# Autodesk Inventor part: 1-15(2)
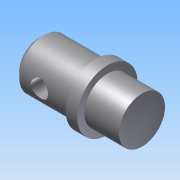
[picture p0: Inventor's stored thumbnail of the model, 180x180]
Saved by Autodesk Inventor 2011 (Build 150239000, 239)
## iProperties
Created: 2014-02
Part Number: 1-15(2)
Document SubType Name: Modeling
Designer: Administrator
Density: 1 g/cm^3
Author: Administrator
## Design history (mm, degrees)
sketch "草图1"
  geometry: L1 (-8.931, 4.3)-(-8.931, 0); L2 (-8.931, 4.3)-(1.069, 4.3); L3 (1.069, 4.3)-(1.069, 5.245); L4 (1.069, 5.245)-(3.069, 5.245); L5 (3.069, 5.245)-(3.069, 4); L6 (3.069, 4)-(9.069, 4); L7 (-8.931, 0)-(9.069, 0); L8 (9.069, 0)-(9.069, 4); C1 r 1.5 at (-5.572, 0); 2 further points
  constraints: 16 end point, 4 parallel, 3 perpendicular, 1 centre point, 1 horizontal alignment, 1 point on line
  dimensions: "d1" = 3 diameter of C1; "d6" = 4 distance of L7.end L6.end; "d8" = 4.3 distance between parallel lines of L7 L2; "d10" = 10 distance of L1.start L2.end; "d11" = 18 distance between parallel lines of L8 L1; "d13" = 2 distance of L3.end L4.end
revolve "旋转1" sketch "草图1" stored, may be unused: angle "d0" = 90 deg
node "工作平面1"
sketch "草图2"
  geometry: L1 (10.036, 4.077)-(10.036, -4.077) reference; L2 (8.931, 4.3)-(8.931, -4.3) reference; C1 r 1.5 at (4.465, 0); 3 further points; 1 other entity
  constraints: 1 centre point, 1 other
  dimensions: "d3" = 3 diameter of C1
extrude "拉伸1" cut sketch "草图2" stored distance "d4" = 10; taper "d5" = 0 deg
chamfer "倒角1" distance "d14" = 1; stored, may be unused: second distance "d15" = 2, angle "d16" = 45 deg
node "实体1"
other parameters: "d2" = -6
